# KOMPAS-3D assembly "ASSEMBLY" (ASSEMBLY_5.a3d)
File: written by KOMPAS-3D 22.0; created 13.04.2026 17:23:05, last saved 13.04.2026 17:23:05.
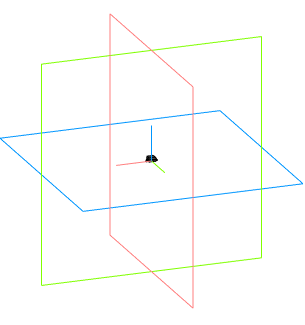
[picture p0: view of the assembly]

Document properties: Автор: Andrey; Полное имя файла: C:\Users\User1\Documents\ASSEMBLY_5.a3d

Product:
- Component [detail]: Body  | qty 1  | source file: Body_6.m3d
- Component [detail]: FilletPinL  | qty 1  | source file: FilletPinL.m3d
- Component [detail]: FilletPinR  | qty 1  | source file: FilletPinR.m3d
- Part/product: ASSEMBLY

Referenced files in C:\Users\User1\Documents\: Body_6.m3d, FilletPinL.m3d, FilletPinR.m3d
